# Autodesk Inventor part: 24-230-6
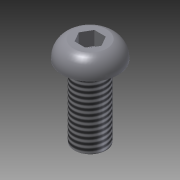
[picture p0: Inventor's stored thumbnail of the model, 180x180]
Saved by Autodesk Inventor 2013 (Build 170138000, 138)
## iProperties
Created: 2004-10
Part Number: 24-230-6
Material: Stahl (hohe Festigk., niedr. Legier.)
Description: SCREW, PARKER IPS, FLAT HEAD, M6X30
Document SubType Name: Modeling
Designer: Autodesk, Inc.
Manufacturer: Standard
Standards Organization: Custom
Catalog Web Link: http://www.parker.com/ead/cm1.asp?cmid=809
Vendor: PARKER IPS
Mass: 10.8823 g
Surface Area: 9.37524 cm^2
Volume: 1.38805 cm^3
Density: 7.84 g/cm^3
CAGE: 1LJX3
Dept. ID: Product Design
Description #2: ---
Finish #1: ---
Finish #2: ---
Material ID: ---
Project Number: ---
Author: Autodesk, Inc.
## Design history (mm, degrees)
derived "2X-YYY-ZZ IPS Screws.ipt"
body "Solid1"
tag "TaggingFeature2"
feature "Solid1::2X-YYY-ZZ IPS Screws.ipt" dims "ScaleForDerivedMember" = 10
